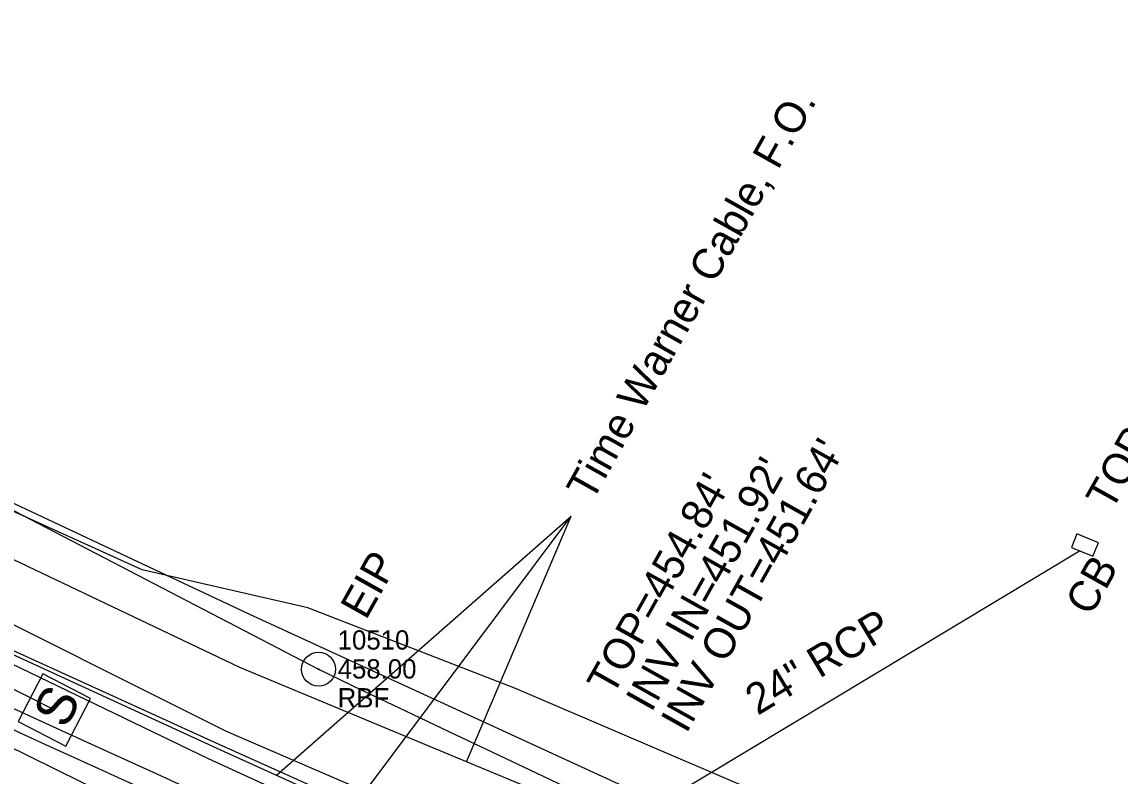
# Model space of a CAD drawing. Extents: x 2074109 to 2077820, y 741079 to 746031.
# Drawn here: x 2076238.9 to 2076381.3, y 743032.9 to 743130.7 of the extents above; entities that cross this region are included whole.
import ezdxf

# ---------------------------------------------------------------- set-up
doc = ezdxf.new("R2010")
doc.units = 0
for name, color, linetype in [('Exist Property Iron Pin CELL', 7, 'Continuous'), ('Exist Property Iron Pin Cogo Comment', 7, 'Continuous'), ('Exist Property Iron Pin Cogo Elevation', 7, 'Continuous'), ('Exist Property Iron Pin Cogo Number', 7, 'Continuous'), ('Exist Property Iron Pin Text', 7, 'Continuous'), ('Exist Right of Way Line', 7, 'Continuous'), ('Exist Roads Curbs', 7, 'Continuous'), ('Exist Roads EOP', 7, 'Continuous'), ('Exist Structure Minor Catch Basin', 7, 'Continuous'), ('Exist Structure Minor Catch Basin Text', 7, 'Continuous'), ('Exist Structure Minor Catch Basin Top Elevation', 7, 'Continuous'), ('Exist Structure Minor Drop Inlet Top Elevation', 7, 'Continuous'), ('Exist Structure Minor Pipes RCP 24 Inch', 7, 'Continuous'), ('Exist Structure Minor Pipes RCP 24 Inch Invert', 7, 'Continuous'), ('Exist Structure Minor Pipes RCP 24 Inch Text', 7, 'Continuous'), ('Exist Utilities Gas UG Line SUE LOS B', 7, 'Continuous'), ('Exist Utilities Other Traffic Signal Box CELL', 7, 'Continuous'), ('Exist Utilities Power UG Cable SUE LOS B', 7, 'Continuous'), ('Exist Utilities Telephone UG Conduit SUE LOS B', 7, 'Continuous'), ('Exist Utilities Telephone UG FO SUE LOS B', 7, 'Continuous'), ('Exist Utilities TV UG FO Cable SUE LOS B', 7, 'Continuous'), ('Exist Utilities TV UG FO Cable SUE LOS B Leader', 7, 'Continuous'), ('Exist Utilities TV UG FO Cable SUE LOS B Text', 7, 'Continuous'), ('Exist Utilities Water UG Line SUE LOS B', 7, 'Continuous'), ('Exist Vegetation Woods Line', 7, 'Continuous')]:
    doc.layers.add(name, color=color, linetype=linetype)

msp = doc.modelspace()

# ---------------------------------------------------------------- linework, layer by layer
at = {"layer": 'Exist Property Iron Pin CELL'}
for radius in [2.2, 0.0707]:
    msp.add_circle((2076277.33, 743046.77), radius, dxfattribs=at)
at = {"layer": 'Exist Right of Way Line'}
msp.add_line((2076208.04, 743082.83), (2076277.33, 743046.77), dxfattribs=at)
msp.add_arc((2077913.16, 746443.07), 3769.72, 244.28216, 256.42986, dxfattribs=at)
at = {"layer": 'Exist Roads Curbs'}
msp.add_lwpolyline([(2076235.65, 743042.63), (2076239.67, 743040.81), (2076244.47, 743038.62), (2076249.87, 743036.16), (2076255.89, 743033.4), (2076262.45, 743030.39), (2076269.51, 743027.14), (2076276.98, 743023.7), (2076284.65, 743020.16), (2076291.22, 743017.13), (2076296.58, 743014.66), (2076301.26, 743012.49), (2076305.24, 743010.63), (2076307.8, 743009.44), (2076308.49, 743009.11)], dxfattribs=at)
at = {"layer": 'Exist Roads EOP'}
msp.add_lwpolyline([(2076235.2, 743040.06), (2076241.92, 743037.01), (2076248.79, 743033.9), (2076256.2, 743030.54), (2076264.49, 743026.73), (2076274.02, 743022.31), (2076284.56, 743017.43), (2076295.85, 743012.23), (2076304.99, 743008.03), (2076309.1, 743006.12), (2076312.36, 743004.59), (2076318.98, 743001.47), (2076328.02, 742997.2), (2076338.57, 742992.18), (2076349.87, 742986.8), (2076361.16, 742981.46), (2076371.4, 742976.61), (2076379.55, 742972.73), (2076387.23, 742969.07)], dxfattribs=at)
at = {"layer": 'Exist Structure Minor Catch Basin'}
msp.add_lwpolyline([(2076374.98, 743062.56), (2076377.77, 743061.42), (2076378.49, 743063.18), (2076375.7, 743064.32)], close=True, dxfattribs=at)
at = {"layer": 'Exist Structure Minor Pipes RCP 24 Inch'}
msp.add_line((2076376.04, 743062.08), (2076317.35, 743026.81), dxfattribs=at)
at = {"layer": 'Exist Utilities Gas UG Line SUE LOS B'}
msp.add_lwpolyline([(2075996.08, 743328.1), (2076028.05, 743254.56), (2076033.74, 743242.95), (2076036.74, 743229.04), (2076040.38, 743218.46), (2076044.43, 743205.24), (2076049.54, 743192.7), (2076055.99, 743180.15), (2076059.89, 743167.76), (2076068.56, 743138.12), (2076068.53, 743138.04), (2076073.69, 743123.02), (2076077.5, 743117.33), (2076094.04, 743108.87), (2076148.84, 743082.51), (2076220.11, 743045.2), (2076259.6, 743025.74), (2076318.3, 742998.06), (2076360.46, 742978.31), (2076403.47, 742958.09), (2076437.14, 742944.03)], dxfattribs=at)
at = {"layer": 'Exist Utilities Other Traffic Signal Box CELL'}
msp.add_line((2076243.07, 743041.49), (2076243.07, 743041.49), dxfattribs=at)
msp.add_lwpolyline([(2076244.57, 743036.81), (2076247.76, 743042.99), (2076241.58, 743046.17), (2076238.39, 743039.99), (2076244.57, 743036.81)], dxfattribs=at)
at = {"layer": 'Exist Utilities Power UG Cable SUE LOS B'}
msp.add_lwpolyline([(2076006.41, 743187.86), (2076006.4, 743187.87), (2076014.64, 743174.79), (2076032.56, 743157.65), (2076035.3, 743152.7), (2076055.02, 743138.31), (2076080.32, 743125.75), (2076098, 743114.25), (2076150.92, 743086.68), (2076224.69, 743050.77), (2076243.07, 743041.49)], dxfattribs=at)
at = {"layer": 'Exist Utilities Telephone UG Conduit SUE LOS B'}
msp.add_lwpolyline([(2075672.89, 743341.39), (2075736.54, 743308.65), (2075796.69, 743278.05), (2075867.04, 743238.5), (2075921.9, 743209.46), (2075960.48, 743187.73), (2076008.51, 743166.58), (2076026.12, 743160.68), (2076048.83, 743145.45), (2076053.46, 743153.14), (2076083.51, 743134.83), (2076100.14, 743126.62), (2076153.6, 743096.75), (2076227.57, 743057.65), (2076265.35, 743038.75), (2076325.02, 743012.99), (2076370.03, 742993.2), (2076407.51, 742976.75), (2076444.05, 742959.06)], dxfattribs=at)
at = {"layer": 'Exist Utilities Telephone UG FO SUE LOS B'}
msp.add_lwpolyline([(2075889.86, 743237.93), (2075895.59, 743228.51), (2075924.94, 743209.93), (2075958.41, 743190.94), (2075991.59, 743174.52), (2076008.89, 743165.82), (2076027.41, 743153.76), (2076049.09, 743142.61), (2076053.91, 743141.46), (2076059.01, 743140.99), (2076072.19, 743141.15), (2076089.2, 743137.48), (2076101.24, 743131.5), (2076156.95, 743103.14), (2076158.66, 743102.38), (2076232.03, 743071), (2076268.38, 743053.9), (2076329.12, 743025.97), (2076375.16, 743007.01), (2076410.42, 742991.12), (2076450.75, 742973.66)], dxfattribs=at)
at = {"layer": 'Exist Utilities TV UG FO Cable SUE LOS B'}
for points in [[(2076079.54, 743131.47), (2076088.75, 743134.71), (2076100.72, 743130.58), (2076230.37, 743064.49), (2076267.06, 743047.02), (2076329.64, 743021), (2076373.86, 743003.6), (2076375.16, 743000.31), (2076408.25, 742984.45), (2076447.17, 742965.86)], [(2076083.6, 743130.45), (2076090.74, 743121.86), (2076099.09, 743116.59), (2076149.07, 743090.83), (2076226.38, 743054.36), (2076264.41, 743037.05), (2076323.79, 743010.38), (2076368.03, 742988.68), (2076370.37, 742987.68), (2076405.31, 742971.65), (2076441.93, 742954.46)], [(2076083.6, 743130.45), (2076090.73, 743121.86), (2076098.84, 743116.1), (2076148.75, 743090.35), (2076226.27, 743053.92), (2076264.15, 743036.52), (2076323.36, 743009.63), (2076368, 742988.68), (2076369.51, 742985.96), (2076404.98, 742971), (2076441.71, 742953.97)]]:
    msp.add_lwpolyline(points, dxfattribs=at)
at = {"layer": 'Exist Utilities TV UG FO Cable SUE LOS B Leader'}
for p in [(2076271.88, 743033.05), (2076282.14, 743029.26), (2076296.5, 743034.78)]:
    msp.add_line(p, (2076310.11, 743066.61), dxfattribs=at)
at = {"layer": 'Exist Utilities Water UG Line SUE LOS B'}
msp.add_lwpolyline([(2075822.78, 743289.56), (2075827.27, 743285.77), (2075840.04, 743277.92), (2075859.15, 743265.03), (2075885.55, 743248.54), (2075912.1, 743233.66), (2075938.18, 743219.55), (2075978.32, 743202.62), (2076004.37, 743190.72), (2076024.72, 743179.9), (2076058.28, 743162.37), (2076071.85, 743150.27), (2076099.45, 743125.15), (2076149.87, 743092.08), (2076225.21, 743053.38), (2076263, 743035.19), (2076322.41, 743007.95), (2076371.93, 742982.13), (2076406.73, 742964.12), (2076444.22, 742949.22), (2076483.69, 742930.03)], dxfattribs=at)
at = {"layer": 'Exist Vegetation Woods Line'}
msp.add_lwpolyline([(2076452.8, 742978.14), (2076411.57, 742997.51), (2076372.36, 743015), (2076332.34, 743031.67), (2076302.88, 743044.27), (2076275.96, 743054.74), (2076254.46, 743059.65), (2076231.08, 743070.25), (2076212.24, 743079.14), (2076197.2, 743091.07), (2076186.86, 743102.52), (2076184.31, 743113.37), (2076185.7, 743122.79), (2076183.65, 743131.36), (2076180.3, 743139.76), (2076155.91, 743151.77), (2076143.65, 743150.09), (2076137.94, 743137.99), (2076140.74, 743129.52), (2076148.47, 743119.68), (2076149.8, 743116.21), (2076142.91, 743116.48), (2076122.59, 743129.22), (2076117.94, 743141.67)], dxfattribs=at)

# ---------------------------------------------------------------- texts
at = {"layer": 'Exist Property Iron Pin Cogo Comment'}
msp.add_text('RBF', height=2.5, dxfattribs=at).set_placement((2076279.81, 743041.82))
at = {"layer": 'Exist Property Iron Pin Cogo Elevation'}
msp.add_text('458.00', height=2.5, dxfattribs=at).set_placement((2076279.81, 743045.57))
at = {"layer": 'Exist Property Iron Pin Cogo Number'}
msp.add_text('10510', height=2.5, dxfattribs=at).set_placement((2076279.81, 743049.32))
at = {"layer": 'Exist Property Iron Pin Text'}
msp.add_text('EIP', height=4, rotation=60.742, dxfattribs=at).set_placement((2076283.48, 743053.04))
at = {"layer": 'Exist Structure Minor Catch Basin Text'}
msp.add_text('CB', height=4, rotation=60.742, dxfattribs=at).set_placement((2076377.51, 743053.53))
at = {"layer": 'Exist Structure Minor Catch Basin Top Elevation'}
msp.add_text("TOP=470.41'", height=4, rotation=60.7411, dxfattribs=at).set_placement((2076380.18, 743067.16))
at = {"layer": 'Exist Structure Minor Drop Inlet Top Elevation'}
msp.add_text("TOP=454.84'", height=4, rotation=60.7411, dxfattribs=at).set_placement((2076315.47, 743043.17))
at = {"layer": 'Exist Structure Minor Pipes RCP 24 Inch Invert'}
for s, p in [("INV OUT=451.64'", (2076325.04, 743038.32)), ("INV IN=451.92'", (2076320.49, 743041.07))]:
    msp.add_text(s, height=4, rotation=60.7411, dxfattribs=at).set_placement(p)
at = {"layer": 'Exist Structure Minor Pipes RCP 24 Inch Text'}
msp.add_text('24" RCP', height=4, rotation=31.0035, dxfattribs=at).set_placement((2076334.28, 743040.72))
at = {"layer": 'Exist Utilities Other Traffic Signal Box CELL'}
msp.add_text('S', height=5, rotation=62.7319, dxfattribs=at).set_placement((2076244.55, 743038.89))
at = {"layer": 'Exist Utilities TV UG FO Cable SUE LOS B Text'}
msp.add_text('Time Warner Cable, F.O.', height=4, rotation=60.742, dxfattribs=at).set_placement((2076312.81, 743068.38))

doc.saveas('drawing.dxf')
